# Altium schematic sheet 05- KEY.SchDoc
size A4
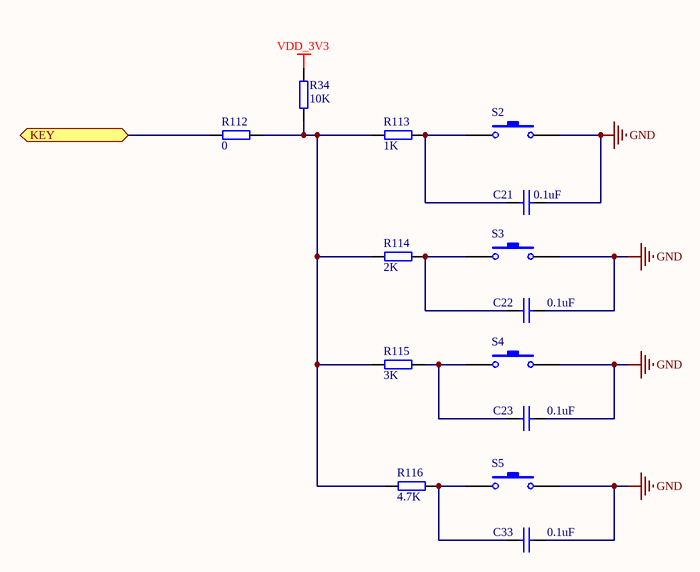
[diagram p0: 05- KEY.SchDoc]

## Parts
C21  0.1uF  [C0402]
C22  0.1uF  [C0402]
C23  0.1uF  [C0402]
C33  0.1uF  [C0402]
R34  10K  [R0402]
R112  0  [R0402]
R113  1K  [R0402]
R114  2K  [R0402]
R115  3K  [R0402]
R116  4.7K  [R0402]
S2  SW-PB  [KEY(3.2*4.2)]  (value not drawn)
S3  SW-PB  [KEY(3.2*4.2)]  (value not drawn)
S4  SW-PB  [KEY(3.2*4.2)]  (value not drawn)
S5  SW-PB  [KEY(3.2*4.2)]  (value not drawn)

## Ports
KEY (bidir)

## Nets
GND: C21.2 C22.2 C23.2 C33.2 S2.2 S3.2 S4.2 S5.2
VDD_3V3: R34.1
KEY: R112.1 ; port KEY
NetC21_1: C21.1 R113.2 S2.1
NetC22_1: C22.1 R114.2 S3.1
NetC23_1: C23.1 R115.2 S4.1
NetC33_1: C33.1 R116.2 S5.1
NetR34_2: R34.2 R112.2 R113.1 R114.1 R115.1 R116.1

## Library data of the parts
C21-C23 C33 = 电容: Capacitor
R34 R112-R116 = 电阻Ω: Resistor
S2-S5 = SW-PB: Switch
